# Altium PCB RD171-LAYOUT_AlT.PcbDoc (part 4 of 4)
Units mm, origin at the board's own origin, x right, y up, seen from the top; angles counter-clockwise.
Board outline 318.5 x 127 mm, 6 copper layers (TOP, Mid-Layer 1, Mid-Layer 2, Mid-Layer 3, Mid-Layer 4, BOTTOM), stack 1.422 mm thick; 473 components, 225 nets, 1188 pads, 1192 vias.
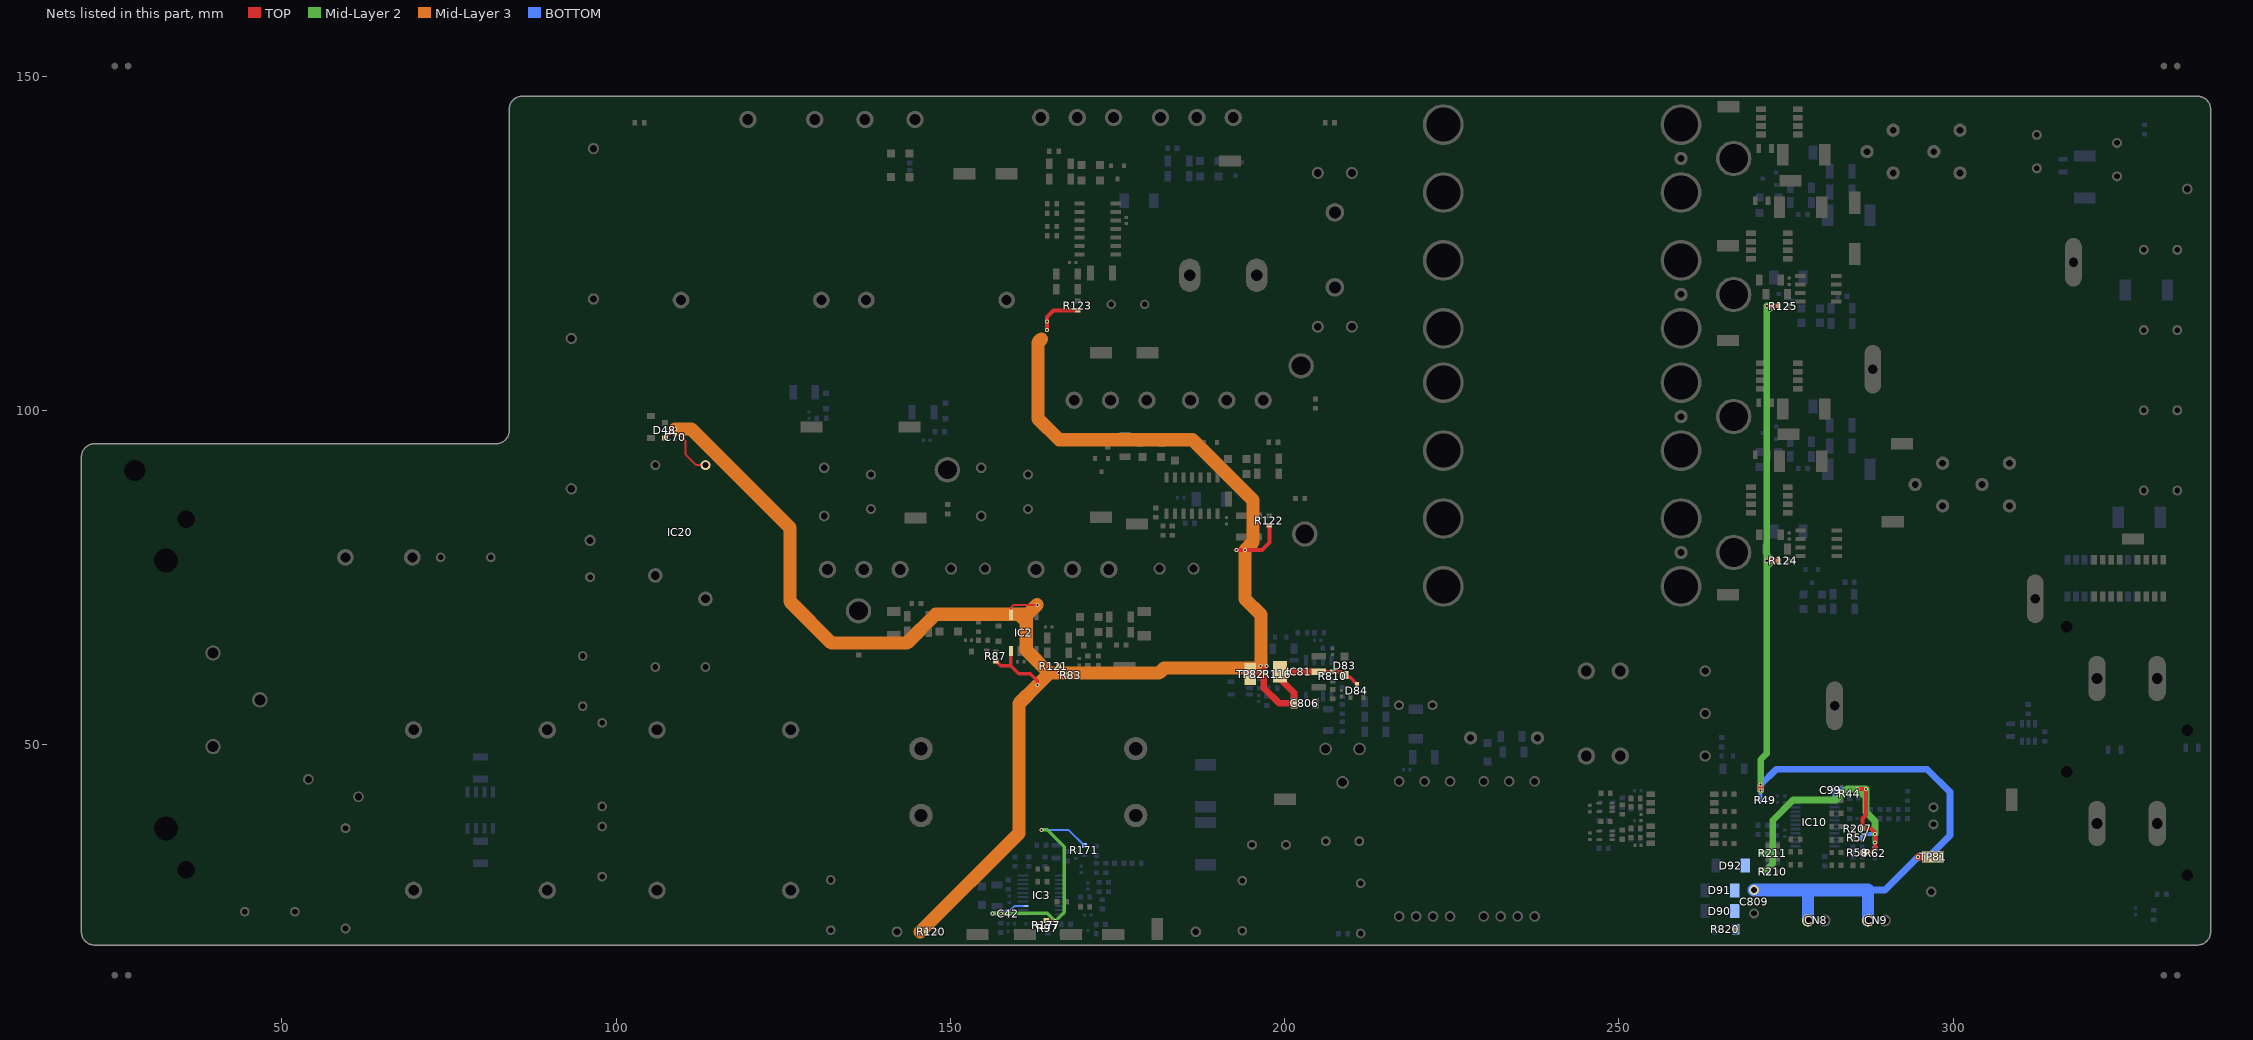
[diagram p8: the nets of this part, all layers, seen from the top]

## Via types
v1: diameter 0.6, hole 0.3, TOP to BOTTOM, 1184 vias
v2: diameter 7, hole 3.2, TOP to BOTTOM, 8 vias

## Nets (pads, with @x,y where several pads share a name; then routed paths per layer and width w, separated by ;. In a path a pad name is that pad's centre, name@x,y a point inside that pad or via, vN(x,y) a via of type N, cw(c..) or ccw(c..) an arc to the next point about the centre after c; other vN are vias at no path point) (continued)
VCC12R0_1: C70.2 C806.1 D48.C D83.A D84.C IC2.1 IC2.8 IC20.1 IC81.OUT_0 IC81.OUT_1 R83.2 R87.2 R116.1 R120.1 R121.1 R122.1 R123.1 R810.1 TP82.1 | length 316.6
  TOP w0.3: D48.C@107.3,95.85 107.9,96.45 C70.2@108.633,96.45 ; C70.2@108.8,96.45 109.35,96.45 110.35,95.45 110.35,93.4 111.95,91.8 IC20.1@113.35,91.8 ; C70.2@108.8,96.604 v1(108.8,97.2) ; IC2.8@159.045,70.05 159.045,70.5 159.445,70.9 v1(163,70.9)
  TOP w0.4: C70.2@108.633,96.45 108.8,96.45 C70.2@108.8,96.475 C70.2@108.8,96.604
  TOP w0.5: R87.2@156.8,62.5 157.495,61.805 159.045,61.805 ; IC2.1@159.045,64 159.045,61.805 ; v1(163,58.9) 163,59.55 161.95,60.6 160.25,60.6 159.045,61.805 ; v1(166.15,60.7) 166.5,60.35 R83.2@167.25,60.35 ; IC81.OUT_0@205.1,60.9 R810.1@207.2,60.9 208.45,60.9 D83.A@208.95,60.4 209.3,60.05 209.77,60.05 210.77,59.05 D84.C@210.8,59.05
  TOP w0.6: v1(145.5,22) R120.1@146.4,22 ; IC2.8@159.045,69.4 IC2.8@159.045,70.05 ; v1(164.45,112.05) v1(164.45,113.3) 164.45,113.95 165.45,114.95 R123.1@169.025,114.95 R123.1@169.05,114.95 ; v1(192.8,79.1) v1(194.05,79.1) 196.6,79.1 197.75,80.25 R122.1@197.75,82.75 ; TP82.1@194.85,60.6 194.985,60.735 196.85,60.735
  TOP w0.7: v1(166.15,60.7) R121.1@166.15,61.7
  TOP w0.95: IC81.OUT_1@199.25,60.9 IC81.OUT_0@205.05,60.9
  TOP w1: 196.85,61.35 196.85,60.735 196.85,58.5 199.15,56.2 C806.1@201.4,56.2 201.4,57.75 199.25,59.9 IC81.OUT_1@199.25,60.9
  Mid-Layer 3 w2: v1(108.8,97.2) 111.25,97.2 126,82.45 126,71.4 132.2,65.2 143.5,65.2 147.8,69.5 160.25,69.5 ; v1(145.5,22) 160.25,36.75 160.25,56.15 v1(163,58.9) 164.8,60.7 ; v1@162.95,70.9 161.55,69.5 161.35,69.5 ; 163.62,110.67 163.1,110.15 163.1,98.75 166.25,95.6 186.2,95.6 195.25,86.55 195.25,80.3 v1(194.05,79.1) 194.05,71.8 196.45,69.4 v1@196.45,61.75 ; 196.35,61.45 181.95,61.45 181.2,60.7 v1(166.15,60.7) 164.8,60.7 ; 160.25,69.5 161.35,68.4 ; 160.25,69.5 161.35,69.5 ; 161.35,68.4 161.35,64.15 164.8,60.7 ; 161.35,68.4 161.35,69.5
  BOTTOM w0.6: v1(164.45,112.05) v1(164.45,113.3) ; v1(192.8,79.1) v1(194.05,79.1)
  other v1: 196.35,60.85 197.25,60.85 196.35,61.75 197.25,61.75
VCC12R0_2: C809.2 CN8.1 CN9.1 D90.C D91.C D92.C R49.1 R124.1 R125.1 R820.2 TP81.1 | length 167.9
  TOP w0.6: v1(271.2,43.1) v1(271.2,44) ; v1(272.1,77.5) v1(272.95,77.5) R124.1@273.9,77.5 ; v1(272.1,115.6) v1(272.95,115.6) R125.1@273.9,115.6
  TOP w1: v1(294.75,33.2) TP81.1@297,33.2
  Mid-Layer 2 w1: v1(271.2,43.1) v1(271.2,44) 271.2,47.75 272.1,48.65 272.1,76.65 ; 272.1,76.65 v1(272.95,77.5) ; 272.1,76.65 v1(272.1,77.5) ; v1(272.1,77.5) 272.1,78.35 ; v1(272.1,77.5) v1(272.95,77.5) ; 272.1,78.35 v1(272.95,77.5) ; 272.1,78.35 272.1,114.75 ; 272.1,114.75 v1(272.95,115.6) v1(272.1,115.6) 272.1,114.75
  BOTTOM w0.6: R49.1@271.2,41.65 v1(271.2,43.1) ; v1(272.1,77.5) v1(272.95,77.5) ; v1(272.1,115.6) v1(272.95,115.6)
  BOTTOM w1: v1(271.2,43.1) v1(271.2,44) 273.5,46.3 296.1,46.3 299.5,42.9 299.5,36.4 296.3,33.2 v1(294.75,33.2) 289.8,28.25 287.25,28.25
  BOTTOM w1.8: CN8.1@278.25,23.7 278.25,28.25 ; CN9.1@287.25,23.7 287.25,28.25
  BOTTOM w2: C809.2@270.2,28.25 278.25,28.25 287.25,28.25
VREF: C99.2 IC10.1 R44.2 R57.2 R58.2 R62.2 R207.2 R210.2 R211.2 | length 68.7
  TOP w0.6: v1(285.7,43.35) v1(286.95,43.35) 286.95,39.46 286.4,38.91 R207.2@286.4,37.45 ; R58.2@286.4,33.85 287.7,33.85 288.3,34.45 v1(288.3,35.35) v1(288.3,36.65) 288.3,36.85 287.7,37.45 R207.2@286.45,37.45
  Mid-Layer 2 w0.8: v1(288.3,35.35) v1(288.3,36.65)
  Mid-Layer 2 w1: v1(271.4,31.2) 272,31.2 273,32.2 273,33.15 ; 272.3,33.75 v1(271.4,33.75) 272.4,33.75 ; v1(288.3,36.65) 288.3,38.55 286.95,39.9 286.95,42.1 ; 272.4,33.75 273,33.15 ; 272.4,33.75 273,34.35 ; 272.4,33.75 273,33.75 ; 272.4,33.75 273,33.15 ; 272.4,33.75 273,34.35 ; 272.4,33.75 273,33.75 ; 273,33.15 273,33.75 ; 273,33.15 273,33.75 ; 273,33.75 273,34.35 ; 273,33.75 273,34.35 ; 273,34.35 273,38.65 276.05,41.7 282.45,41.7 284.1,43.35 v1(285.7,43.35) ; v1(285.7,43.35) v1(286.95,43.35) 286.95,42.1 ; v1(285.7,43.35) 286.95,42.1
  BOTTOM w0.4: v1(271.4,33.75) R211.2@272.3,33.75
  BOTTOM w0.45: IC10.1@282.175,41.95 C99.2@282.175,43.125 ; C99.2@282.175,43.15 282.95,43.15
  BOTTOM w0.6: v1(271.4,31.2) 271.65,30.95 R210.2@272.25,30.95 ; 282.95,43.15 283.15,43.35 R44.2@284.5,43.35 v1(285.7,43.35) v1(286.95,43.35) ; R57.2@286.4,36.05 287,36.65 v1(288.3,36.65) v1(288.3,35.35) R62.2@288.3,34.4
VREF_PFC: C42.2 IC3.13 R97.2 R171.2 R177.2 | length 40.9
  TOP w0.3: R177.2@164.35,23.7 165.2,23.7 165.211,23.698 v1(165.65,23.6)
  Mid-Layer 2 w0.5: v1(156.3,24.75) v1(157.55,24.75) 164.5,24.75 v1(165.65,23.6) 167,24.95 167,34.75 164.5,37.25 v1(163.65,37.25)
  BOTTOM w0.3: C42.2@158.65,25.175 159.125,25.4 159.6,25.875 IC3.13@160.85,25.875 ; v1(163.65,37.25) 167.64,37.25 R171.2@170.05,34.84
  BOTTOM w0.4: R97.2@164.55,23.2 164.95,23.6 v1(165.65,23.6)
  BOTTOM w0.45: v1(157.55,24.75) 157.925,24.75 158.35,25.175 C42.2@158.65,25.175
  BOTTOM w0.6: v1(156.3,24.75) v1(157.55,24.75)
pads on no net: cam1. cam2. cam3. cam4. CN1. CN6. CN7. D8. D9. D22.NC D23.NC D24.NC D25.NC D26.NC D27.NC D28.NC D29.NC D49. D80. D84.NC IC1.1 IC1.4 IC1.5 IC1.8 IC4.4 IC4.8 IC4.9 IC4.10 IC4.14 IC5.4 IC5.8 IC5.9 IC5.10 IC5.14 IC6.1 IC6.8 IC7.1 IC7.8 IC10.16 IC11.4 IC11.5 IC13.2 IC14.2 IC15.2 IC16.2 IC21.1 IC22.1 IC23.1 IC24.1 T4.4 T4.6 T4.7 T8.2 T8.7 T8.10 T8.11 T8.14

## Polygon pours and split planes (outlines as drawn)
no net on Top Overlay "TOPOVERLAY226" (solid, pour order 0): 21 vertices, not listed, extent 247.45,23.575 249.7,26.125
no net on Top Overlay "TOPOVERLAY225" (solid, pour order 0): 256.5,23.6 cw(c256.5,23.65) 256.45,23.65 256.45,26.05 cw(c256.5,26.05) 256.5,26.1 257.8,26.1 cw(c257.8,25.45) 258.084,24.865 cw(c257.875,24.25) 257.875,23.6
no net on Top Overlay "TOPOVERLAY224" (solid, pour order 0): 258.741,23.6 cw(c258.741,23.65) 258.693,23.663 259.365,26.063 cw(c259.413,26.05) 259.413,26.1 260.337,26.1 cw(c260.337,26.05) 260.385,26.063 261.057,23.663 cw(c261.009,23.65) 261.009,23.6 260.413,23.6 cw(c260.413,23.65) 260.365,23.637 260.25,24.05 259.5,24.05 259.385,23.637 cw(c259.337,23.65) 259.337,23.6
SIGN360 on TOP "TOP61" (solid, pour order 199): 35 vertices, not listed, extent 255.3,52 283.65,87.35
N07003 on TOP "TOP60" (solid, pour order 198): 43 vertices, not listed, extent 255.3,102.25 289.375,125.95
LGND on TOP "TOP59" (solid, pour order 197): 62 vertices, not listed, extent 274.525,83.5 285.059,108.25
LGND on TOP "TOP58" (solid, pour order 196): 194 vertices, not listed, extent 274.525,26.841 338,146.5
P48V on TOP "TOP57" (solid, pour order 195): 17 vertices, not listed, extent 314.5,53.25 335.75,76.225
CONN004 on TOP "TOP56" (solid, pour order 194): 127 vertices, not listed, extent 294.4,68 333.45,143.05
N07429 on TOP "TOP55" (solid, pour order 193): 54 vertices, not listed, extent 255.3,90.3 275.325,108.25
N17045153 on TOP "TOP54" (solid, pour order 192): 273.2,90.8 cw(c273.2,90.85) 273.15,90.85 273.15,92.317 ccw(c272.95,92.317) 273.091,92.459 272.909,92.641 ccw(c272.767,92.5) 272.767,92.7 272,92.7 cw(c272,92.75) 271.95,92.75 271.95,93.95 cw(c272,93.95) 272,94 274.8,94 cw(c274.8,93.95) 274.85,93.95 274.85,90.85 cw(c274.8,90.85) 274.8,90.8
N17045135 on TOP "TOP53" (solid, pour order 191): 273.2,128.8 cw(c273.2,128.85) 273.15,128.85 273.15,130.317 ccw(c272.95,130.317) 273.091,130.459 272.909,130.641 ccw(c272.767,130.5) 272.767,130.7 272,130.7 cw(c272,130.75) 271.95,130.75 271.95,131.95 cw(c272,131.95) 272,132 274.8,132 cw(c274.8,131.95) 274.85,131.95 274.85,128.85 cw(c274.8,128.85) 274.8,128.8
SIG135 on TOP "TOP52" (solid, pour order 190): 56 vertices, not listed, extent 255.3,128.9 275.325,146.25
N07369 on TOP "TOP51" (solid, pour order 189): 21 vertices, not listed, extent 263.25,122.27 273.825,139.45
SIG115 on TOP "TOP50" (solid, pour order 188): 19 vertices, not listed, extent 263.25,84.27 273.825,100.9
SIG6 on TOP "TOP49" (solid, pour order 187): 43 vertices, not listed, extent 91.55,114 140.4,136.5
CONN003 on TOP "TOP48" (solid, pour order 186): 45 vertices, not listed, extent 209.15,71.49 226.05,101.85
SIGN355 on TOP "TOP47" (solid, pour order 185): 20 vertices, not listed, extent 207.75,84.25 212.45,94.95
N17045822 on TOP "TOP46" (solid, pour order 184): 273.7,136.6 cw(c273.7,136.65) 273.65,136.65 273.65,138.117 ccw(c273.45,138.117) 273.591,138.259 273.409,138.441 ccw(c273.267,138.3) 273.267,138.5 272.5,138.5 cw(c272.5,138.55) 272.45,138.55 272.45,139.75 cw(c272.5,139.75) 272.5,139.8 275.3,139.8 cw(c275.3,139.75) 275.35,139.75 275.35,136.65 cw(c275.3,136.65) 275.3,136.6
SIG121 on TOP "TOP45" (solid, pour order 183): 17 vertices, not listed, extent 273.7,78.45 275.7,82.2
N17045143 on TOP "TOP44" (solid, pour order 182): 273.7,98.6 cw(c273.7,98.65) 273.65,98.65 273.65,100.117 ccw(c273.45,100.117) 273.591,100.259 273.409,100.441 ccw(c273.267,100.3) 273.267,100.5 272.5,100.5 cw(c272.5,100.55) 272.45,100.55 272.45,101.75 cw(c272.5,101.75) 272.5,101.8 275.3,101.8 cw(c275.3,101.75) 275.35,101.75 275.35,98.65 cw(c275.3,98.65) 275.3,98.6
SIG124 on TOP "TOP43" (solid, pour order 181): 17 vertices, not listed, extent 273.7,116.55 275.7,120.3
PN on TOP "TOP42" (solid, pour order 180): 28 vertices, not listed, extent 163.6,117.3 168.25,123.6
SIGN270 on TOP "TOP41" (solid, pour order 179): 168.675,116 cw(c168.675,116.05) 168.625,116.05 168.625,117.025 168.54,117.11 cw(c168.575,117.146) 168.525,117.146 168.525,123.5 cw(c168.575,123.5) 168.575,123.55 169.475,123.55 cw(c169.475,123.5) 169.525,123.5 169.525,117.146 cw(c169.475,117.146) 169.51,117.11 169.425,117.025 169.425,116.05 cw(c169.375,116.05) 169.375,116
no net on TOP "TOP40" (solid, pour order 178): 49 vertices, not listed, extent 21,13 337.5,18.714
N14565980 on TOP "TOP39" (solid, pour order 177): 21 vertices, not listed, extent 220.7,49.9 222.65,51.7
VCC12R0_1 on TOP "TOP38" (solid, pour order 176): 17 vertices, not listed, extent 196,60.15 197.6,62.1
no net on TOP "TOP37" (solid, pour order 175): 50 vertices, not listed, extent 21,96.286 337.5,154
FG3 on TOP "TOP36" (solid, pour order 174): 22 vertices, not listed, extent 80.525,62.525 87.175,70.075
SIG91 on TOP "TOP35" (solid, pour order 173): 20 vertices, not listed, extent 189.625,83.75 198.1,84.75
PN on TOP "TOP34" (solid, pour order 172): 22 vertices, not listed, extent 190,80.55 196.6,83.3
SIG82 on TOP "TOP33" (solid, pour order 171): 182.988,141.1 179.813,141.1 179.813,146.5 182.988,146.5
SIG249 on TOP "TOP32" (solid, pour order 170): 188.437,141.1 185.262,141.1 185.262,146.5 188.437,146.5
PN on TOP "TOP31" (solid, pour order 169): 193.887,141.1 190.712,141.1 190.712,146.5 193.887,146.5
N05004 on TOP "TOP30" (solid, pour order 168): 165.088,141.1 161.913,141.1 161.913,146.5 165.088,146.5
SIG249 on TOP "TOP29" (solid, pour order 167): 175.987,141.1 172.812,141.1 172.812,146.5 175.987,146.5
SIG205 on TOP "TOP28" (solid, pour order 166): 195.213,104.2 198.388,104.2 198.388,98.8 195.213,98.8
PN on TOP "TOP27" (solid, pour order 165): 184.312,104.2 187.487,104.2 187.487,98.8 184.312,98.8
CONN002 on TOP "TOP26" (solid, pour order 164): 166.913,104.2 170.088,104.2 170.088,98.8 166.913,98.8
SIG104 on TOP "TOP25" (solid, pour order 163): 164.05,66.45 cw(c164.05,66.5) 164,66.5 164,67.8 cw(c164.05,67.8) 164.05,67.85 164.4,67.85 cw(c164.4,67.8) 164.45,67.8 164.45,67.2 164.985,66.665 cw(c164.95,66.629) 165,66.629 165,66.5 cw(c164.95,66.5) 164.95,66.45
SIG6 on TOP "TOP24" (solid, pour order 162): 136.562,114 cw(c136.562,114.15) 136.456,114.044 134.694,115.806 cw(c134.8,115.912) 134.65,115.912 134.65,118.85 cw(c134.8,118.85) 134.8,119 140.25,119 cw(c140.25,118.85) 140.4,118.85 140.4,115.462 cw(c140.25,115.462) 140.356,115.356 139.044,114.044 cw(c138.938,114.15) 138.938,114
SIGN364 on TOP "TOP23" (solid, pour order 161): 23 vertices, not listed, extent 103.875,59.85 115.85,72.9
SIG6 on TOP "TOP22" (solid, pour order 160): 17 vertices, not listed, extent 91.45,102.1 101,111.6
SIG6 on TOP "TOP21" (solid, pour order 159): 128.2,27.25 cw(c128.2,27.3) 128.15,27.3 128.15,37.55 cw(c128.2,37.55) 128.2,37.6 135.1,37.6 cw(c135.1,37.55) 135.15,37.55 135.15,30.871 cw(c135.1,30.871) 135.135,30.835 131.565,27.265 cw(c131.529,27.3) 131.529,27.25
SIG8 on TOP "TOP20" (solid, pour order 158): 18 vertices, not listed, extent 96.05,74 109,82.1
SIGN364 on TOP "TOP19" (solid, pour order 157): 93.75,71.2 cw(c93.75,71.35) 93.6,71.35 93.6,76.05 cw(c93.75,76.05) 93.75,76.2 97.55,76.2 cw(c97.55,76.05) 97.7,76.05 97.7,71.35 cw(c97.55,71.35) 97.55,71.2
SIG18 on TOP "TOP18" (solid, pour order 156): 166.662,78.9 169.837,78.9 169.837,73.5 166.662,73.5
PN on TOP "TOP17" (solid, pour order 155): 161.212,78.9 164.387,78.9 164.387,73.5 161.212,73.5
SIGN267 on TOP "TOP16" (solid, pour order 154): 140.912,78.9 144.087,78.9 144.087,73.5 140.912,73.5
PN on TOP "TOP15" (solid, pour order 153): 143.43,146.03 145.97,146.03 145.97,141.78 143.43,141.78
SIG6 on TOP "TOP14" (solid, pour order 152): 135.93,146.03 138.47,146.03 138.47,141.78 135.93,141.78
SIG8 on TOP "TOP13" (solid, pour order 151): 128.43,146.03 130.97,146.03 130.97,141.78 128.43,141.78
PFC_OUT on TOP "TOP12" (solid, pour order 150): 118.43,146.03 120.97,146.03 120.97,141.78 118.43,141.78
PFC_OUT on TOP "TOP11" (solid, pour order 149): 153.88,78.26 156.48,78.26 156.48,74.36 153.88,74.36
SIG12 on TOP "TOP10" (solid, pour order 148): 148.8,78.26 151.4,78.26 151.4,74.36 148.8,74.36
SIG8 on TOP "TOP9" (solid, pour order 147): 18 vertices, not listed, extent 96.05,74 109,82.1
SIGN364 on TOP "TOP8" (solid, pour order 146): 93.6,72.2 93.6,75.2 94.6,76.2 97.55,76.2 cw(c97.55,76.05) 97.7,76.05 97.7,71.35 cw(c97.55,71.35) 97.55,71.2 94.6,71.2
SIG2 on TOP "TOP7" (solid, pour order 145): 30 vertices, not listed, extent 40.59,22.8 72.25,48.7
SIG200 on TOP "TOP6" (solid, pour order 144): 94.8,35.75 cw(c94.8,35.8) 94.75,35.8 94.75,41.7 cw(c94.8,41.7) 94.8,41.75 101.05,41.75 cw(c101.05,41.7) 101.1,41.7 101.1,35.8 cw(c101.05,35.8) 101.05,35.75
SIG200 on TOP "TOP5" (solid, pour order 143): 18 vertices, not listed, extent 104.5,26.5 109.5,31.65
SIG200 on TOP "TOP4" (solid, pour order 142): 17 vertices, not listed, extent 86.4,26.5 91.4,31.65
SIG199 on TOP "TOP3" (solid, pour order 141): 92.95,50.75 cw(c92.95,50.9) 92.8,50.9 92.8,55.338 cw(c92.95,55.338) 92.844,55.444 94.206,56.806 cw(c94.312,56.7) 94.312,56.85 96.038,56.85 cw(c96.038,56.7) 96.144,56.806 97.456,55.494 cw(c97.35,55.388) 97.5,55.388 97.5,50.9 cw(c97.35,50.9) 97.35,50.75
FG2 on TOP "TOP2" (solid, pour order 140): 24.5,27.35 cw(c24.65,27.35) 24.65,27.5 29.576,27.5 cw(c29.576,27.2) 29.788,27.412 32.912,24.288 cw(c32.7,24.076) 33,24.076 33,23.562 cw(c32.85,23.562) 32.956,23.456 30.088,20.588 cw(c29.876,20.8) 29.876,20.5 26,20.5 cw(c26,22) 24.5,22
FG2 on TOP "TOP1" (solid, pour order 139): 24.5,27.35 cw(c24.65,27.35) 24.65,27.5 29.576,27.5 cw(c29.576,27.2) 29.788,27.412 32.912,24.288 cw(c32.7,24.076) 33,24.076 33,23.562 cw(c32.85,23.562) 32.956,23.456 30.088,20.588 cw(c29.876,20.8) 29.876,20.5 26,20.5 cw(c26,22) 24.5,22
LGND on Mid-Layer 1 "MID167" (solid, pour order 138): 151 vertices, not listed, extent 210.9,20.5 338,146.5
P48V on Mid-Layer 1 "MID164" (solid, pour order 135): 17 vertices, not listed, extent 320.65,66.1 330.25,70.9
CONN004 on Mid-Layer 1 "MID165" (solid, pour order 136): 17 vertices, not listed, extent 315.35,79.9 322.55,87.1
PN on Mid-Layer 1 "MID166" (solid, pour order 137): 331 vertices, not listed, extent 102.255,20.5 255.4,146.5
no net on Mid-Layer 1 "MID163" (solid, pour order 134): 50 vertices, not listed, extent 21,96.286 337.5,154
no net on Mid-Layer 1 "MID162" (solid, pour order 133): 49 vertices, not listed, extent 21,13 337.5,18.714
CONN002 on Mid-Layer 2 "MID274" (solid, pour order 132): 116 vertices, not listed, extent 166.65,99 225.5,145.79
CONN004 on Mid-Layer 2 "MID273" (solid, pour order 131): 44 vertices, not listed, extent 294.4,68 333.45,143.1
P48V on Mid-Layer 2 "MID272" (solid, pour order 130): 17 vertices, not listed, extent 314.5,53.25 335.8,76.225
SIG249 on Mid-Layer 2 "MID271" (solid, pour order 129): 53 vertices, not listed, extent 171.55,116.5 194.55,145.45
no net on Mid-Layer 2 "MID270" (solid, pour order 128): 49 vertices, not listed, extent 21,13 337.5,18.714
no net on Mid-Layer 2 "MID269" (solid, pour order 127): 50 vertices, not listed, extent 21,96.286 337.5,154
SIG8 on Mid-Layer 2 "MID268" (solid, pour order 126): 21 vertices, not listed, extent 107.975,114.875 132.5,145.2
VCC12R0_1 on Mid-Layer 3 "MID385" (solid, pour order 125): 17 vertices, not listed, extent 192.4,77.85 195.05,79.92
VCC12R0_1 on Mid-Layer 3 "MID384" (solid, pour order 124): 194.5,60.45 cw(c194.5,60.55) 194.4,60.55 194.4,61.709 cw(c194.5,61.709) 194.429,61.779 195.921,63.271 cw(c195.991,63.2) 195.991,63.3 196.679,63.3 cw(c196.679,63.25) 196.715,63.285 197.785,62.215 cw(c197.75,62.179) 197.8,62.179 197.8,60.771 cw(c197.75,60.771) 197.785,60.735 197.515,60.465 cw(c197.479,60.5) 197.479,60.45
CONN002 on Mid-Layer 3 "MID383" (solid, pour order 123): 127 vertices, not listed, extent 166.65,99 225.5,145.79
VCC12R0_1 on Mid-Layer 3 "MID382" (solid, pour order 122): 23 vertices, not listed, extent 162.708,109.758 164.95,113.8
CONN004 on Mid-Layer 3 "MID381" (solid, pour order 121): 20 vertices, not listed, extent 314.95,79.9 316.47,81.1
no net on Mid-Layer 3 "MID380" (solid, pour order 120): 50 vertices, not listed, extent 21,96.286 337.5,154
no net on Mid-Layer 3 "MID379" (solid, pour order 119): 49 vertices, not listed, extent 21,13 337.5,18.714
SIG8 on Mid-Layer 3 "MID378" (solid, pour order 118): 21 vertices, not listed, extent 107.975,114.875 132.5,145.2
SIG8 on Mid-Layer 3 "MID377" (solid, pour order 117): 97.024,115.25 cw(c97.024,115.55) 96.812,115.338 96.538,115.612 cw(c96.75,115.824) 96.45,115.824 96.45,118.15 cw(c96.75,118.15) 96.75,118.45 98.85,118.45 cw(c98.85,118.15) 99.15,118.15 99.15,115.55 cw(c98.85,115.55) 98.85,115.25
SIG1 on Mid-Layer 3 "MID376" (solid, pour order 116): 67.25,47.6 cw(c67.25,47.65) 67.2,47.65 67.2,51.779 cw(c67.25,51.779) 67.215,51.815 69.035,53.635 cw(c69.071,53.6) 69.071,53.65 70.329,53.65 cw(c70.329,53.6) 70.365,53.635 72.185,51.815 cw(c72.15,51.779) 72.2,51.779 72.2,47.65 cw(c72.15,47.65) 72.15,47.6
FG4 on Mid-Layer 3 "MID375" (solid, pour order 115): 94.55,20.5 cw(c94.55,20.65) 94.4,20.65 94.4,23.85 cw(c94.55,23.85) 94.55,24 95.254,24 cw(c95.254,23.85) 95.404,23.859 ccw(c97.9,24) 100.396,23.859 cw(c100.546,23.85) 100.546,24 101.25,24 cw(c101.25,23.85) 101.4,23.85 101.4,22.2 101.706,21.894 cw(c101.6,21.788) 101.75,21.788 101.75,20.65 cw(c101.6,20.65) 101.6,20.5
LGND on Mid-Layer 4 "MID494" (solid, pour order 114): 153 vertices, not listed, extent 210.9,20.5 338,146.5
P48V on Mid-Layer 4 "MID491" (solid, pour order 111): 17 vertices, not listed, extent 320.65,66.1 330.25,70.9
CONN004 on Mid-Layer 4 "MID492" (solid, pour order 112): 17 vertices, not listed, extent 315.35,79.9 322.55,87.1
PN on Mid-Layer 4 "MID493" (solid, pour order 113): 332 vertices, not listed, extent 102.255,20.5 255.4,146.5
no net on Mid-Layer 4 "MID490" (solid, pour order 110): 50 vertices, not listed, extent 21,96.286 337.5,154
no net on Mid-Layer 4 "MID489" (solid, pour order 109): 49 vertices, not listed, extent 21,13 337.5,18.714
SIG8 on Mid-Layer 4 "MID488" (solid, pour order 108): 97.024,115.25 cw(c97.024,115.55) 96.812,115.338 96.538,115.612 cw(c96.75,115.824) 96.45,115.824 96.45,118.15 cw(c96.75,118.15) 96.75,118.45 98.85,118.45 cw(c98.85,118.15) 99.15,118.15 99.15,115.55 cw(c98.85,115.55) 98.85,115.25
SIG1 on Mid-Layer 4 "MID487" (solid, pour order 107): 67.25,47.55 cw(c67.25,47.6) 67.2,47.6 67.2,51.779 cw(c67.25,51.779) 67.215,51.815 69.035,53.635 cw(c69.071,53.6) 69.071,53.65 70.329,53.65 cw(c70.329,53.6) 70.365,53.635 72.185,51.815 cw(c72.15,51.779) 72.2,51.779 72.2,47.6 cw(c72.15,47.6) 72.15,47.55
FG4 on Mid-Layer 4 "MID486" (solid, pour order 106): 94.55,20.5 cw(c94.55,20.65) 94.4,20.65 94.4,23.85 cw(c94.55,23.85) 94.55,24 95.254,24 cw(c95.254,23.85) 95.404,23.859 ccw(c97.9,24) 100.396,23.859 cw(c100.546,23.85) 100.546,24 101.25,24 cw(c101.25,23.85) 101.4,23.85 101.4,22.2 101.706,21.894 cw(c101.6,21.788) 101.75,21.788 101.75,20.65 cw(c101.6,20.65) 101.6,20.5
LGND on BOTTOM "BOTTOM198" (solid, pour order 105): 28 vertices, not listed, extent 276.025,102.05 285.05,108.25
LGND on BOTTOM "BOTTOM197" (solid, pour order 104): 96 vertices, not listed, extent 276.025,53.5 337,146.5
FG6 on BOTTOM "BOTTOM196" (solid, pour order 103): 35 vertices, not listed, extent 327,20.5 338,50.2
LGND on BOTTOM "BOTTOM195" (solid, pour order 102): 45 vertices, not listed, extent 314.5,24.85 336.1,51.3
P48V on BOTTOM "BOTTOM194" (solid, pour order 101): 43 vertices, not listed, extent 314.5,48.6 335.1,76.225
LGND on BOTTOM "BOTTOM193" (solid, pour order 100): 35 vertices, not listed, extent 274.525,83.5 283.1,90.4
LGND on BOTTOM "BOTTOM192" (solid, pour order 99): 18 vertices, not listed, extent 273.15,135.3 277.4,137.2
LGND on BOTTOM "BOTTOM191" (solid, pour order 98): 18 vertices, not listed, extent 273.15,97.3 277.4,99.2
N07119 on BOTTOM "BOTTOM190" (solid, pour order 97): 33 vertices, not listed, extent 276.825,118.85 293.751,143.05
CONN004 on BOTTOM "BOTTOM189" (solid, pour order 96): 130 vertices, not listed, extent 295.9,68 329.5,143.05
SIG135 on BOTTOM "BOTTOM188" (solid, pour order 95): 53 vertices, not listed, extent 255.3,128.9 275.325,146.25
N07369 on BOTTOM "BOTTOM187" (solid, pour order 94): 27 vertices, not listed, extent 263.25,118.85 273.825,139.45
N07429 on BOTTOM "BOTTOM186" (solid, pour order 93): 46 vertices, not listed, extent 255.3,90.3 275.325,108.25
SIG115 on BOTTOM "BOTTOM185" (solid, pour order 92): 27 vertices, not listed, extent 263.25,80.85 273.825,100.9
N07003 on BOTTOM "BOTTOM184" (solid, pour order 91): 26 vertices, not listed, extent 255.3,108.75 270,125.95
SIGN360 on BOTTOM "BOTTOM183" (solid, pour order 90): 30 vertices, not listed, extent 255.3,70.45 270,87.35
SIG8 on BOTTOM "BOTTOM182" (solid, pour order 89): 27 vertices, not listed, extent 90.8,86.35 105.3,119.15
CONN003 on BOTTOM "BOTTOM181" (solid, pour order 88): 66 vertices, not listed, extent 209.15,71.49 226.05,117.45
SIGN355 on BOTTOM "BOTTOM180" (solid, pour order 87): 55 vertices, not listed, extent 172.365,84.4 212.45,102.15
CONN003 on BOTTOM "BOTTOM179" (solid, pour order 86): 51 vertices, not listed, extent 194.2,117.35 218.379,137.05
N14557584 on BOTTOM "BOTTOM178" (solid, pour order 85): 200.171,34.25 cw(c200.171,34.3) 200.135,34.265 199.465,34.935 cw(c199.5,34.971) 199.45,34.971 199.45,35.36 cw(c199.5,35.36) 199.5,35.41 201.4,35.41 cw(c201.4,35.36) 201.45,35.36 201.45,34.821 cw(c201.4,34.821) 201.435,34.785 200.915,34.265 cw(c200.879,34.3) 200.879,34.25
N16785059 on BOTTOM "BOTTOM177" (solid, pour order 84): 28 vertices, not listed, extent 226.8,48.1 233.1,52
N66342 on BOTTOM "BOTTOM176" (solid, pour order 83): 19 vertices, not listed, extent 229,43.95 230.9,48.05
N14557584 on BOTTOM "BOTTOM175" (solid, pour order 82): 23 vertices, not listed, extent 235,46.625 238.8,52
PN on BOTTOM "BOTTOM174" (solid, pour order 81): 17 vertices, not listed, extent 221.9,44.4 225.5,49.2
PN on BOTTOM "BOTTOM173" (solid, pour order 80): 21 vertices, not listed, extent 214.65,48.7 217.4,57.2
N66362 on BOTTOM "BOTTOM172" (solid, pour order 79): 18 vertices, not listed, extent 210.55,48.4 212.45,57.2
SIGN355 on BOTTOM "BOTTOM171" (solid, pour order 78): 172.363,104.2 175.538,104.2 175.538,98.8 172.363,98.8
N07083 on BOTTOM "BOTTOM170" (solid, pour order 77): 43 vertices, not listed, extent 276.825,80.85 299.55,101.6
LGND on BOTTOM "BOTTOM169" (solid, pour order 76): 36 vertices, not listed, extent 274.525,121.5 283.1,128.4
N14553110 on BOTTOM "BOTTOM168" (solid, pour order 75): 43 vertices, not listed, extent 231.5,21 265.2,32.95
VCC12R0_2 on BOTTOM "BOTTOM167" (solid, pour order 74): 34 vertices, not listed, extent 266.6,21.6 288.595,32.95
FG5 on BOTTOM "BOTTOM166" (solid, pour order 73): 25 vertices, not listed, extent 196.45,20.5 208.4,25.829
LGND on BOTTOM "BOTTOM165" (solid, pour order 72): 19 vertices, not listed, extent 209.1,21.025 211.875,22.475
LGND on BOTTOM "BOTTOM164" (solid, pour order 71): 280.1,89.9 280.1,96.7 279.9,96.9 279.471,96.9 cw(c279.471,96.95) 279.435,96.915 279.265,97.085 cw(c279.3,97.121) 279.25,97.121 279.25,98.529 cw(c279.3,98.529) 279.265,98.565 279.535,98.835 cw(c279.571,98.8) 279.571,98.85 282.05,98.85 cw(c282.05,98.8) 282.1,98.8 282.1,89.6 280.4,89.6
SIG126 on BOTTOM "BOTTOM163" (solid, pour order 70): 17 vertices, not listed, extent 275.55,114.65 278.45,116.75
LGND on BOTTOM "BOTTOM162" (solid, pour order 69): 280.1,127.9 280.1,134.7 279.9,134.9 279.471,134.9 cw(c279.471,134.95) 279.435,134.915 279.265,135.085 cw(c279.3,135.121) 279.25,135.121 279.25,136.529 cw(c279.3,136.529) 279.265,136.565 279.535,136.835 cw(c279.571,136.8) 279.571,136.85 282.05,136.85 cw(c282.05,136.8) 282.1,136.8 282.1,127.6 280.4,127.6
SIGN373 on BOTTOM "BOTTOM161" (solid, pour order 68): 198.9,104.75 cw(c198.9,104.9) 198.75,104.9 198.75,108.4 cw(c198.9,108.4) 198.9,108.55 202.35,108.55 cw(c202.35,108.4) 202.5,108.4 202.5,104.9 cw(c202.35,104.9) 202.35,104.75
FG7 on BOTTOM "BOTTOM160" (solid, pour order 67): 22 vertices, not listed, extent 328.2,140.95 338,146.5
FG7 on BOTTOM "BOTTOM159" (solid, pour order 66): 331,143 ccw(c334.5,143) 338,143 ccw(c334.5,143)
FG7 on BOTTOM "BOTTOM158" (solid, pour order 65): 331,143 ccw(c334.5,143) 338,143 ccw(c334.5,143)
N14565980 on BOTTOM "BOTTOM157" (solid, pour order 64): 218.85,50.2 cw(c218.85,50.25) 218.8,50.25 218.8,51.55 cw(c218.85,51.55) 218.85,51.6 221.2,51.6 221.285,51.685 cw(c221.321,51.65) 221.321,51.7 222.479,51.7 cw(c222.479,51.65) 222.515,51.685 222.635,51.565 cw(c222.6,51.529) 222.65,51.529 222.65,50.371 cw(c222.6,50.371) 222.635,50.335 222.515,50.215 cw(c222.479,50.25) 222.479,50.2
AUX on BOTTOM "BOTTOM156" (solid, pour order 63): 216.45,44.45 cw(c216.45,44.5) 216.4,44.5 216.4,46.25 216.65,46.5 217.95,46.5 cw(c217.95,46.45) 218,46.45 218,45.271 cw(c217.95,45.271) 217.985,45.235 217.959,45.209 ccw(c218.1,45.067) 217.9,45.067 217.9,44.5 cw(c217.85,44.5) 217.85,44.45
N14557584 on BOTTOM "BOTTOM155" (solid, pour order 62): 210.821,34.55 cw(c210.821,34.6) 210.785,34.565 210.415,34.935 cw(c210.45,34.971) 210.4,34.971 210.4,37.6 cw(c210.45,37.6) 210.45,37.65 213.565,37.65 cw(c213.565,37.6) 213.615,37.6 213.615,35.776 cw(c213.565,35.776) 213.6,35.74 212.425,34.565 cw(c212.389,34.6) 212.389,34.55
SIG6 on BOTTOM "BOTTOM154" (solid, pour order 61): 26 vertices, not listed, extent 132.7,114.575 140.4,146
PN on BOTTOM "BOTTOM153" (solid, pour order 60): 184.462,99.913 cw(c184.462,100.063) 184.312,100.063 184.312,104.05 cw(c184.462,104.05) 184.462,104.2 187.338,104.2 cw(c187.338,104.05) 187.487,104.05 187.487,100.062 cw(c187.338,100.062) 187.338,99.913
CONN002 on BOTTOM "BOTTOM152" (solid, pour order 59): 189.913,98.9 cw(c189.913,99.05) 189.763,99.05 189.763,104.05 cw(c189.912,104.05) 189.912,104.2 192.788,104.2 cw(c192.788,104.05) 192.938,104.05 192.938,99.05 cw(c192.788,99.05) 192.788,98.9
SIG206 on BOTTOM "BOTTOM151" (solid, pour order 58): 178.112,99.913 cw(c178.112,100.213) 177.812,100.213 177.812,104.05 cw(c177.962,104.05) 177.962,104.2 180.838,104.2 cw(c180.838,104.05) 180.987,104.05 180.987,100.062 cw(c180.838,100.062) 180.838,99.913
SIG1 on BOTTOM "BOTTOM150" (solid, pour order 57): 24 vertices, not listed, extent 57,33 74.2,47.6
SIG1 on BOTTOM "BOTTOM149" (solid, pour order 56): 67.25,45.9 cw(c67.25,45.95) 67.2,45.95 67.2,51.779 cw(c67.25,51.779) 67.215,51.815 69.035,53.635 cw(c69.071,53.6) 69.071,53.65 70.329,53.65 cw(c70.329,53.6) 70.365,53.635 75.385,48.615 cw(c75.35,48.579) 75.4,48.579 75.4,48.221 cw(c75.35,48.221) 75.385,48.185 73.115,45.915 cw(c73.079,45.95) 73.079,45.9
PFC_OUT on BOTTOM "BOTTOM148" (solid, pour order 55): 38 vertices, not listed, extent 175.205,46.15 187.88,78.26
PFC_OUT on BOTTOM "BOTTOM147" (solid, pour order 54): 19 vertices, not listed, extent 181.1,46.15 192.65,54.35
VCC12R0_1 on BOTTOM "BOTTOM146" (solid, pour order 53): 19 vertices, not listed, extent 196.015,60.535 199.3,62.085
SIGN369 on BOTTOM "BOTTOM145" (solid, pour order 52): 201.25,79 cw(c201.25,79.15) 201.1,79.15 201.1,83.75 cw(c201.25,83.75) 201.25,83.9 204.75,83.9 cw(c204.75,83.75) 204.9,83.75 204.9,79.15 cw(c204.75,79.15) 204.75,79
N16790081 on BOTTOM "BOTTOM144" (solid, pour order 51): 218.55,46 cw(c218.55,46.05) 218.5,46.05 218.5,46.629 cw(c218.55,46.629) 218.515,46.665 218.541,46.691 ccw(c218.4,46.833) 218.6,46.833 218.6,49.15 cw(c218.65,49.15) 218.65,49.2 219.65,49.2 cw(c219.65,49.15) 219.7,49.15 219.7,46.521 cw(c219.65,46.521) 219.685,46.485 219.215,46.015 cw(c219.179,46.05) 219.179,46
PFC_OUT on BOTTOM "BOTTOM143" (solid, pour order 50): 194.621,34.45 cw(c194.621,34.5) 194.585,34.465 193.865,35.185 cw(c193.9,35.221) 193.85,35.221 193.85,36.55 cw(c193.9,36.55) 193.9,36.6 195.8,36.6 cw(c195.8,36.55) 195.85,36.55 195.85,35.021 cw(c195.8,35.021) 195.835,34.985 195.315,34.465 cw(c195.279,34.5) 195.279,34.45
LGND on BOTTOM "BOTTOM142" (solid, pour order 49): 263.121,21.6 cw(c263.121,21.65) 263.085,21.615 262.915,21.785 cw(c262.95,21.821) 262.9,21.821 262.9,22.979 cw(c262.95,22.979) 262.915,23.015 263.085,23.185 cw(c263.121,23.15) 263.121,23.2 264.75,23.2 cw(c264.75,23.15) 264.8,23.15 264.8,21.65 cw(c264.75,21.65) 264.75,21.6
PFC_OUT on BOTTOM "BOTTOM141" (solid, pour order 48): 19 vertices, not listed, extent 117.45,134.25 124.45,146.025
PN on BOTTOM "BOTTOM140" (solid, pour order 47): 143.475,141.78 cw(c143.475,141.855) 143.4,141.855 143.4,145.955 cw(c143.475,145.955) 143.475,146.03 145.925,146.03 cw(c145.925,145.955) 146,145.955 146,141.855 cw(c145.925,141.855) 145.925,141.78
SIG6 on BOTTOM "BOTTOM139" (solid, pour order 46): 135.975,141.78 cw(c135.975,141.855) 135.9,141.855 135.9,145.955 cw(c135.975,145.955) 135.975,146.03 138.425,146.03 cw(c138.425,145.955) 138.5,145.955 138.5,141.855 cw(c138.425,141.855) 138.425,141.78
SIG8 on BOTTOM "BOTTOM138" (solid, pour order 45): 128.475,141.78 cw(c128.475,141.855) 128.4,141.855 128.4,145.955 cw(c128.475,145.955) 128.475,146.03 130.925,146.03 cw(c130.925,145.955) 131,145.955 131,141.855 cw(c130.925,141.855) 130.925,141.78
PFC_OUT on BOTTOM "BOTTOM137" (solid, pour order 44): 118.475,141.78 cw(c118.475,141.855) 118.4,141.855 118.4,145.955 cw(c118.475,145.955) 118.475,146.03 120.925,146.03 cw(c120.925,145.955) 121,145.955 121,141.855 cw(c120.925,141.855) 120.925,141.78
no net on BOTTOM "BOTTOM136" (solid, pour order 43): 49 vertices, not listed, extent 21,13 337.5,18.714
no net on BOTTOM "BOTTOM135" (solid, pour order 42): 50 vertices, not listed, extent 21,96.286 337.5,154
SIG11 on BOTTOM "BOTTOM134" (solid, pour order 41): 18 vertices, not listed, extent 153.862,111.462 160.5,118.1
SIGN355 on BOTTOM "BOTTOM133" (solid, pour order 40): 33 vertices, not listed, extent 166.43,103.75 175.535,141.75
SIG82 on BOTTOM "BOTTOM132" (solid, pour order 39): 182.988,141.1 179.813,141.1 179.813,146.5 182.988,146.5
PN on BOTTOM "BOTTOM131" (solid, pour order 38): 193.887,141.1 190.712,141.1 190.712,146.5 193.887,146.5
N05004 on BOTTOM "BOTTOM130" (solid, pour order 37): 165.088,141.1 161.913,141.1 161.913,146.5 165.088,146.5
SIGN355 on BOTTOM "BOTTOM129" (solid, pour order 36): 170.537,141.1 167.362,141.1 167.362,146.5 170.537,146.5
SIG249 on BOTTOM "BOTTOM128" (solid, pour order 35): 175.987,141.1 172.812,141.1 172.812,146.5 175.987,146.5
CONN002 on BOTTOM "BOTTOM127" (solid, pour order 34): 168.986,98.8 cw(c168.986,98.875) 168.933,98.822 166.934,100.821 cw(c166.987,100.874) 166.913,100.874 166.913,104.125 cw(c166.987,104.125) 166.987,104.2 170.013,104.2 cw(c170.013,104.125) 170.088,104.125 170.088,98.875 cw(c170.013,98.875) 170.013,98.8
SIG86 on BOTTOM "BOTTOM126" (solid, pour order 33): 158.6,26.15 cw(c158.6,26.2) 158.55,26.2 158.55,26.55 cw(c158.6,26.55) 158.6,26.6 159.05,26.6 159.76,27.31 cw(c159.796,27.275) 159.796,27.325 160.2,27.325 cw(c160.2,27.275) 160.25,27.275 160.25,27.075 cw(c160.2,27.075) 160.2,27.025 160.05,27.025 159.19,26.165 cw(c159.154,26.2) 159.154,26.15
PN on BOTTOM "BOTTOM125" (solid, pour order 32): 22 vertices, not listed, extent 158.25,27.1 159.7,28.7
SIG11 on BOTTOM "BOTTOM124" (solid, pour order 31): 43 vertices, not listed, extent 159.2,74.81 182.8,94.03
SIG18 on BOTTOM "BOTTOM123" (solid, pour order 30): 21 vertices, not listed, extent 160.4,73.5 169.835,86.33
PFC_OUT on BOTTOM "BOTTOM122" (solid, pour order 29): 28 vertices, not listed, extent 148.8,46.15 158.7,78.26
SIG12 on BOTTOM "BOTTOM121" (solid, pour order 28): 31 vertices, not listed, extent 136.7,75.575 151.4,95.4
SIG22 on BOTTOM "BOTTOM120" (solid, pour order 27): 24 vertices, not listed, extent 135.688,74.8 140.905,86.125
SIGN364 on BOTTOM "BOTTOM119" (solid, pour order 26): 123.8,49.65 cw(c123.8,49.7) 123.75,49.7 123.75,54.65 cw(c123.8,54.65) 123.8,54.7 125.779,54.7 cw(c125.779,54.65) 125.815,54.685 127.385,53.115 cw(c127.35,53.079) 127.4,53.079 127.4,50.971 cw(c127.35,50.971) 127.385,50.935 126.115,49.665 cw(c126.079,49.7) 126.079,49.65
SIGN364 on BOTTOM "BOTTOM118" (solid, pour order 25): 23 vertices, not listed, extent 103.875,59.85 115.85,72.9
SIG8 on BOTTOM "BOTTOM117" (solid, pour order 24): 18 vertices, not listed, extent 96.05,74 109,82.1
SIGN364 on BOTTOM "BOTTOM116" (solid, pour order 23): 93.6,72.2 93.6,75.2 94.6,76.2 97.55,76.2 cw(c97.55,76.05) 97.7,76.05 97.7,71.35 cw(c97.55,71.35) 97.55,71.2 94.6,71.2
FG3 on BOTTOM "BOTTOM115" (solid, pour order 22): 83.9,62.525 cw(c83.9,62.675) 83.75,62.675 83.75,63.85 cw(c83.9,63.85) 83.9,64 84.9,64 84.9,64.55 cw(c85.05,64.55) 85.05,64.7 86.138,64.7 cw(c86.138,64.55) 86.244,64.656 87.006,63.894 cw(c86.9,63.788) 87.05,63.788 87.05,62.675 cw(c86.9,62.675) 86.9,62.525
FG3 on BOTTOM "BOTTOM114" (solid, pour order 21): 80.675,64.35 cw(c80.675,64.5) 80.525,64.5 80.525,69.925 cw(c80.675,69.925) 80.675,70.075 81.825,70.075 cw(c81.825,69.925) 81.975,69.925 81.975,69.466 ccw(c82.075,69.466) 82.004,69.396 84.706,66.694 cw(c84.6,66.588) 84.75,66.588 84.75,64.5 cw(c84.6,64.5) 84.6,64.35
SIGN371 on BOTTOM "BOTTOM113" (solid, pour order 20): 133.76,68.1 cw(c133.76,68.25) 133.61,68.25 133.61,71.75 cw(c133.76,71.75) 133.76,71.9 140.74,71.9 cw(c140.74,71.75) 140.89,71.75 140.89,68.25 cw(c140.74,68.25) 140.74,68.1
SIGN366 on BOTTOM "BOTTOM112" (solid, pour order 19): 150.179,87.996 cw(c150.073,88.102) 149.967,87.996 146.446,91.517 cw(c146.552,91.623) 146.446,91.729 148.921,94.204 cw(c149.027,94.098) 149.133,94.204 152.654,90.683 cw(c152.548,90.577) 152.654,90.471
SIG18 on BOTTOM "BOTTOM111" (solid, pour order 18): 166.662,78.9 169.837,78.9 169.837,73.5 166.662,73.5
PN on BOTTOM "BOTTOM110" (solid, pour order 17): 130.013,78.9 133.188,78.9 133.188,73.5 130.013,73.5
PFC_OUT on BOTTOM "BOTTOM109" (solid, pour order 16): 185.08,78.26 187.68,78.26 187.68,74.36 185.08,74.36
PFC_OUT on BOTTOM "BOTTOM108" (solid, pour order 15): 153.88,78.26 156.48,78.26 156.48,74.36 153.88,74.36
SIG12 on BOTTOM "BOTTOM107" (solid, pour order 14): 148.8,78.26 151.4,78.26 151.4,74.36 148.8,74.36
SIGN371 on BOTTOM "BOTTOM106" (solid, pour order 13): 133.76,68.1 cw(c133.76,68.25) 133.61,68.25 133.61,71.75 cw(c133.76,71.75) 133.76,71.9 140.74,71.9 cw(c140.74,71.75) 140.89,71.75 140.89,68.25 cw(c140.74,68.25) 140.74,68.1
SIGN366 on BOTTOM "BOTTOM105" (solid, pour order 12): 150.179,87.996 cw(c150.073,88.102) 149.967,87.996 146.446,91.517 cw(c146.552,91.623) 146.446,91.729 148.921,94.204 cw(c149.027,94.098) 149.133,94.204 152.654,90.683 cw(c152.548,90.577) 152.654,90.471
SIG8 on BOTTOM "BOTTOM104" (solid, pour order 11): 97.024,115.25 cw(c97.024,115.55) 96.812,115.338 96.538,115.612 cw(c96.75,115.824) 96.45,115.824 96.45,118.15 cw(c96.75,118.15) 96.75,118.45 98.85,118.45 cw(c98.85,118.15) 99.15,118.15 99.15,115.55 cw(c98.85,115.55) 98.85,115.25
SIG2 on BOTTOM "BOTTOM103" (solid, pour order 10): 29 vertices, not listed, extent 40.59,22.8 72.25,48.7
SIG200 on BOTTOM "BOTTOM102" (solid, pour order 9): 94.8,35.75 cw(c94.8,35.8) 94.75,35.8 94.75,41.7 cw(c94.8,41.7) 94.8,41.75 101.05,41.75 cw(c101.05,41.7) 101.1,41.7 101.1,35.8 cw(c101.05,35.8) 101.05,35.75
SIG200 on BOTTOM "BOTTOM101" (solid, pour order 8): 17 vertices, not listed, extent 86.4,26.5 91.4,31.65
SIG200 on BOTTOM "BOTTOM100" (solid, pour order 7): 18 vertices, not listed, extent 104.5,26.5 109.5,31.65
SIG2 on BOTTOM "BOTTOM99" (solid, pour order 6): 57.55,21.5 cw(c57.55,21.65) 57.4,21.65 57.4,24.1 cw(c57.55,24.1) 57.55,24.25 62,24.25 cw(c62,24.1) 62.15,24.1 62.15,21.65 cw(c62,21.65) 62,21.5
SIG199 on BOTTOM "BOTTOM98" (solid, pour order 5): 94.35,50.75 cw(c94.35,50.9) 94.2,50.9 94.2,55.338 cw(c94.35,55.338) 94.244,55.444 95.606,56.806 cw(c95.712,56.7) 95.712,56.85 97.438,56.85 cw(c97.438,56.7) 97.544,56.806 98.856,55.494 cw(c98.75,55.388) 98.9,55.388 98.9,50.9 cw(c98.75,50.9) 98.75,50.75
FG4 on BOTTOM "BOTTOM97" (solid, pour order 4): 94.55,20.5 cw(c94.55,20.65) 94.4,20.65 94.4,23.85 cw(c94.55,23.85) 94.55,24 95.254,24 cw(c95.254,23.85) 95.404,23.859 ccw(c97.9,24) 100.396,23.859 cw(c100.546,23.85) 100.546,24 101.25,24 cw(c101.25,23.85) 101.4,23.85 101.4,22.2 101.706,21.894 cw(c101.6,21.788) 101.75,21.788 101.75,20.65 cw(c101.6,20.65) 101.6,20.5
SIG2 on BOTTOM "BOTTOM96" (solid, pour order 3): 57.55,21.5 cw(c57.55,21.65) 57.4,21.65 57.4,24.1 cw(c57.55,24.1) 57.55,24.25 62,24.25 cw(c62,24.1) 62.15,24.1 62.15,21.65 cw(c62,21.65) 62,21.5
SIG199 on BOTTOM "BOTTOM95" (solid, pour order 2): 92.95,50.75 cw(c92.95,50.9) 92.8,50.9 92.8,55.338 cw(c92.95,55.338) 92.844,55.444 94.206,56.806 cw(c94.312,56.7) 94.312,56.85 96.038,56.85 cw(c96.038,56.7) 96.144,56.806 97.456,55.494 cw(c97.35,55.388) 97.5,55.388 97.5,50.9 cw(c97.35,50.9) 97.35,50.75
no net on Bottom Solder "BOTTOMSOLDER223" (solid, pour order 0): 202.55,104.7 198.7,104.7 198.7,108.6 202.55,108.6
no net on Bottom Solder "BOTTOMSOLDER222" (solid, pour order 0): 189.71,104.05 cw(c189.91,104.05) 189.91,104.25 192.79,104.25 cw(c192.79,104.05) 192.99,104.05 192.99,99.05 cw(c192.79,99.05) 192.79,98.85 189.91,98.85 cw(c189.91,99.05) 189.71,99.05
no net on Bottom Solder "BOTTOMSOLDER221" (solid, pour order 0): 177.76,104.06 cw(c177.96,104.06) 177.96,104.26 180.84,104.26 cw(c180.84,104.06) 181.04,104.06 181.04,100.06 cw(c180.84,100.06) 180.84,99.86 178.06,99.86 cw(c178.06,100.16) 177.76,100.16
no net on Bottom Solder "BOTTOMSOLDER220" (solid, pour order 0): 184.26,104.06 cw(c184.46,104.06) 184.46,104.26 187.34,104.26 cw(c187.34,104.06) 187.54,104.06 187.54,100.06 cw(c187.34,100.06) 187.34,99.86 184.46,99.86 cw(c184.46,100.06) 184.26,100.06
no net on Bottom Solder "BOTTOMSOLDER219" (solid, pour order 0): 201.05,78.95 201.05,83.95 204.95,83.95 204.95,78.95
no net on Bottom Solder "BOTTOMSOLDER218" (solid, pour order 0): 166.61,78.95 169.89,78.95 169.89,73.46 166.61,73.46
no net on Bottom Solder "BOTTOMSOLDER217" (solid, pour order 0): 179.95,74.76 179.95,78.31 182.65,78.31 182.65,75.23 182.18,74.76
no net on Bottom Solder "BOTTOMSOLDER216" (solid, pour order 0): 185.03,78.31 187.73,78.31 187.73,74.31 185.03,74.31
no net on Bottom Solder "BOTTOMSOLDER215" (solid, pour order 0): 153.83,78.31 156.53,78.31 156.53,74.31 153.83,74.31
no net on Bottom Solder "BOTTOMSOLDER214" (solid, pour order 0): 148.75,78.31 151.45,78.31 151.45,74.31 148.75,74.31
no net on Bottom Solder "BOTTOMSOLDER213" (solid, pour order 0): 135.63,78.95 138.47,78.95 138.47,74.75 135.63,74.75
no net on Bottom Solder "BOTTOMSOLDER212" (solid, pour order 0): 129.96,78.95 133.24,78.95 133.24,73.45 129.96,73.45
no net on Bottom Solder "BOTTOMSOLDER211" (solid, pour order 0): 172.31,104.25 175.59,104.25 175.59,98.75 172.31,98.75
no net on Bottom Solder "BOTTOMSOLDER210" (solid, pour order 0): 166.86,104.25 170.14,104.25 170.14,98.75 168.93,98.75 166.86,100.82
no net on Bottom Solder "BOTTOMSOLDER209" (solid, pour order 0): 146.268,91.622 149.027,94.383 152.835,90.575 150.075,87.815
no net on Bottom Solder "BOTTOMSOLDER208" (solid, pour order 0): 133.55,68.05 133.55,71.95 140.95,71.95 140.95,68.05
no net on Bottom Solder "BOTTOMSOLDER207" (solid, pour order 0): 190.662,146.55 193.937,146.55 193.937,141.05 190.662,141.05
no net on Bottom Solder "BOTTOMSOLDER206" (solid, pour order 0): 179.763,146.55 183.038,146.55 183.038,141.05 179.763,141.05
no net on Bottom Solder "BOTTOMSOLDER205" (solid, pour order 0): 172.758,146.55 176.037,146.55 176.037,141.05 172.758,141.05
no net on Bottom Solder "BOTTOMSOLDER204" (solid, pour order 0): 167.307,146.55 170.587,146.55 170.587,141.05 167.307,141.05
no net on Bottom Solder "BOTTOMSOLDER203" (solid, pour order 0): 161.857,146.55 165.138,146.55 165.138,141.05 161.857,141.05
no net on Bottom Solder "BOTTOMSOLDER202" (solid, pour order 0): 143.35,141.75 143.35,146.1 146.05,146.1 146.05,141.75
no net on Bottom Solder "BOTTOMSOLDER201" (solid, pour order 0): 135.85,141.75 135.85,146.1 138.55,146.1 138.55,141.75
no net on Bottom Solder "BOTTOMSOLDER200" (solid, pour order 0): 128.35,141.75 128.35,146.1 131.05,146.1 131.05,141.75
no net on Bottom Solder "BOTTOMSOLDER199" (solid, pour order 0): 118.35,141.75 118.35,146.1 121.05,146.1 121.05,141.75

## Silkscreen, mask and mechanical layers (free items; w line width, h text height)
Top Overlay:
  lines w0.15: 120.35,140.95 121.15,140.95 ; 120.75,140.5 120.75,141.4 ; 142.65,71.25 143.6,70.3 ; 144.458,141.198 145.256,141.198 ; 151.65,71.4 151.95,71.1 156.55,71.1 156.85,71.4 ; 151.8,66 152.05,66.25 156,66.25 156.25,66 ; 152.9,71.1 152.9,66.4 ; 158.762,57.813 158.762,55.812 159.6,54.975 159.6,54.05 162.075,54.05 162.625,54.6 162.625,59.375 162.225,59.375 ; 162.65,58 169.3,58 169.7,58.4 169.7,58.95 ; 166.8,67.85 166.6,67.65 166.6,67.05 ; 168.7,71.05 167.8,71.05 167.8,69.6 168.35,69.6 ; 168.775,63.362 168.775,61.475 169.3,60.95 169.3,59.1 170.5,59.1 ; 168.8,65.85 168.5,66.15 168.5,69.8 168.8,70.1 ; 168.95,70.4 168.7,70.65 168.7,72.85 168.95,73.1 ; 171.2,59.1 172.45,59.1 173,59.65 173,65.55 172.7,65.55 ; 177.7,65.05 177.1,65.65 ; 194.475,68.95 194.475,69.5 ; 211.2,60.95 209.638,59.388 208.412,59.388 207.85,59.95 ; 241.075,42.825 241.075,43.2 241.35,43.475 243.275,43.475 ; 243.8,42.95 243.275,43.475 ; 245.325,37.325 244.25,37.325 244.25,34.4 253.8,34.4 253.8,38.15 253.225,38.15 ; 246.25,41.075 246.25,41.575 246.625,41.95 250.75,41.95 251.25,41.45 ; 247.3,31.975 247.3,34.25 ; 247.575,31.925 247,31.925 247,28.7 254.225,28.7 254.225,32.675 253.45,32.675 ; 253.35,43.225 253.575,43.45 ; 253.4,45.475 253.575,45.3 253.575,43.45 ; 253.55,42.75 253.8,42.5 253.8,40.225 253.575,40 ; 253.675,42.675 253.875,42.875 253.875,43.15 253.575,43.45 ; 281.2,122.1 280.25,121.15 276.65,121.15 275.85,120.35 ; 281.25,84.15 280.3,83.2 276.7,83.2 275.9,82.4 ; 288.35,35.9 287.05,35.9 ; 305.1,32.5 305.65,32.5 ; 143.6,70.3 143.35,70.3 143.6,70.55 143.6,70.3 ; 152.9,66.4 153.05,66.55 152.75,66.55 152.9,66.4 ; 166.6,67.05 166.75,67.2 166.45,67.2 166.6,67.05 ; 168.35,69.6 168.2,69.45 168.2,69.75 168.35,69.6 ; 169.7,58.95 169.55,58.8 169.85,58.8 169.7,58.95 ; 177.1,65.65 177.35,65.65 177.1,65.4 177.1,65.65 ; 207.85,59.95 208.1,59.95 207.85,59.7 207.85,59.95 ; 243.275,43.475 243.525,43.725 244.875,43.725 246.525,42.075 ; 246.525,42.075 246.325,42.075 246.525,42.275 246.525,42.075 ; 247.3,34.25 247.125,34.075 247.475,34.075 247.3,34.25 ; 275.85,120.35 276.05,120.35 275.85,120.55 275.85,120.35 ; 275.9,82.4 276.1,82.4 275.9,82.6 275.9,82.4 ; 287.05,35.9 287.2,35.75 287.2,36.05 287.05,35.9
  lines w0.5: 316.5,26.5 318,26.5 ; 316.5,71.25 318,71.25 ; 317.25,70.5 317.25,72
  text "T6-6" at 264.85,142.8 h0.61
  text "OUTB1" at 150.209,137.185 h0.61
  text "OUTA1" at 156.655,137.174 h0.61
  text "SW" at 187.75,136.75 h0.61
  text "HOT. TEST BEFORE" at 112.32,136.16 h0.71
  text "LGND" at 333.587,135.293 h0.61
  text "TOUCHING ON HEATSINKS" at 112.54,134.26 h0.71
  text "Q11-G" at 269.655,133.442 h0.61
  text "Q13-G" at 287.807,131.355 h0.61 r90
  text "T6-5" at 263.8,126.25 h0.61
  text "OUTF" at 283.657,122.287 h0.61 r90
  text "Q4-G" at 178.035,110.34 h0.61
  text "Q3-G" at 171.084,110.319 h0.61
  text "T6-3" at 264.7,107.75 h0.61
  text "CSB" at 143.032,99.252 h0.61
  text "CSA" at 128.247,99.222 h0.61
  text "Q7-G" at 269.987,95.342 h0.61
  text "Q9-G" at 286.988,94.192 h0.61
  text "FOR CONTINUED PROTECTION AGAINST RISK OF FIRE." at 36.24,88.96 h0.71
  text "REPLACE ONLY WITH SAME TYPE" at 52.29,86.78 h0.71
  text "OUTD1" at 170.616,85.731 h0.61
  text "Q1-G" at 143.066,85.575 h0.61
  text "OUTC1" at 175.143,84.721 h0.61
  text "OUTE" at 285.538,82.442 h0.61
  text "48VOUT" at 329.4,80.3 h0.61
  text "T5-3" at 264.5,74.05 h0.61
  text "250V T15AH" at 59.483,72.276 h0.89
  text "VCC12R0 1" at 194.475,63.175 h0.61 r90
  text "Q2-G" at 178.687,61.843 h0.61
  text "CAUTION" at 62.265,58.31 h2.24
  text "Q80-D" at 197.925,43.425 h0.61
  text "OR-G" at 307,39.95 h0.61 r90
  text "VCC12R0 2" at 299.4,32.5 h0.61
  text "DC450V 2A" at 192.595,30.58 h0.89
  text "LGND" at 295.287,24.793 h0.61
  text "VSENSE" at 173.774,23.897 h0.61
  text "GDA" at 159.657,23.708 h0.61
  text "VINAC" at 165.91,23.711 h0.61
  text "PN" at 188.112,23.708 h0.61
  text "GDB" at 152.598,23.352 h0.61
  text "PN" at 138.531,22.344 h0.61
  text "PFC OUT" at 183.62,20.913 h0.61 r90
Bottom Overlay:
  lines w0.15: 149.912,24.737 150.713,24.737 153.95,21.5 156.7,21.5 ; 150.625,28.05 149.175,28.05 149.175,30.25 146.85,30.25 146.85,32.675 149.175,32.675 149.175,34.775 150.625,34.775 150.625,28.075 ; 150.625,28.7 152.95,28.7 ; 159.3,23.8 159.3,30.325 157.95,30.325 157.95,29.75 153.1,29.75 153.1,25.075 158.05,25.075 158.05,23.9 ; 177.4,29.5 174.5,29.5 ; 177.425,31.375 177.425,26.45 175.175,26.45 175.175,23.8 180.475,23.8 180.475,28.1 180.15,28.1 180.15,31.4 177.425,31.4 ; 196.862,62.312 196.862,60.712 196.862,60.662 196.625,60.425 ; 216.8,57.4 216.1,56.7 216.1,55.3 215.85,55.05 ; 245.15,35.7 245.15,34.6 246,33.75 253.8,33.75 253.8,39.05 253.65,39.2 ; 245.25,27.85 245.25,26.8 246.3,25.75 253.85,25.75 253.85,31.15 253.5,31.5 ; 252.5,44.25 252.5,43.75 ; 253.9,31.15 254.25,31.5 254.25,33.35 253.95,33.65 ; 274.025,29.675 274.275,29.425 274.275,24.9 274.05,24.675 ; 274.025,30.1 274.275,30.35 274.275,35.75 274.05,35.975 ; 274.275,28.425 274.925,28.425 274.925,30.8 274.425,30.8 ; 282.95,88.6 282.65,88.9 280.25,88.9 279.85,89.3 279.85,91.35 279.2,92 ; 283.05,126.6 282.75,126.9 280.35,126.9 279.95,127.3 279.95,129.35 279.3,130 ; 283.65,40.65 284,41 287.05,41 287.05,37.4 287,37.35 287,31.15 284.5,31.15 284.2,31.45 ; 289.675,31.225 290.05,31.6 293.55,31.6 293.55,28.05 293.35,27.85 293.35,22.95 291.15,22.95 290.85,23.25 ; 291.25,31.6 291.25,31.95 290.8,32.4 287.2,32.4 ; 152.95,28.7 152.8,28.85 152.8,28.55 152.95,28.7 ; 156.7,21.5 156.55,21.65 156.55,21.35 156.7,21.5 ; 158.05,23.9 156.875,23.9 156.875,21.15 168.55,21.15 168.55,23.8 158.15,23.8 158.05,23.9 ; 174.5,29.5 174.65,29.65 174.65,29.35 174.5,29.5 ; 196.625,60.425 196.825,60.425 196.625,60.625 196.625,60.425 ; 215.85,55.05 216.05,55.05 215.85,55.25 215.85,55.05 ; 252.5,43.75 252.65,43.9 252.35,43.9 252.5,43.75 ; 253.95,33.65 253.95,33.45 254.15,33.65 253.95,33.65 ; 274.425,30.8 274.55,30.675 274.55,30.925 274.425,30.8 ; 279.2,92 279.4,92 279.2,91.8 279.2,92 ; 279.3,130 279.5,130 279.3,129.8 279.3,130 ; 287.2,32.4 287.35,32.55 287.35,32.25 287.2,32.4 ; 139.525,24.525 139.525,27.075 149.9,27.075 149.9,24.525 139.525,24.525 ; 168.875,25.125 171.793,25.125 172.177,24.741 174.35,24.741 174.35,31 173.9,31 173.9,32.825 171.2,32.825 171.2,27.85 168.875,27.85 168.875,25.125 ; 251.2,39.675 253.825,39.675 253.825,43.6 251.2,43.6 251.2,39.675 ; 251.4,44.25 251.4,48.1 254.4,48.1 254.4,44.25 251.4,44.25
